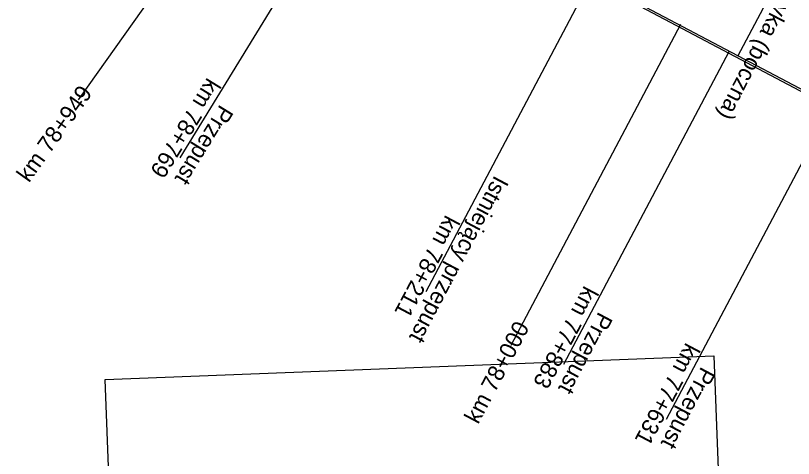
# Model space of a CAD drawing. Extents: x 6540402 to 6566579, y 5525343 to 5532423.
# Drawn here: x 6540402 to 6542041, y 5526352 to 5527285 of the extents above; entities that cross this region are included whole.
import ezdxf

# ---------------------------------------------------------------- set-up
doc = ezdxf.new("R2010")
doc.units = 0
for name, color, linetype in [('TOR_PS_OPIS_T-hektometry projektowane', 7, 'Continuous'), ('TOR_PS_OPIS_T-opisy dodatkowe', 7, 'Continuous'), ('TOR_PS_T-tory projektowane', 7, 'Continuous')]:
    doc.layers.add(name, color=color, linetype=linetype)

msp = doc.modelspace()

# ---------------------------------------------------------------- linework, layer by layer
at = {"layer": 'DEFPOINTS'}
msp.add_lwpolyline([(6541918.8, 5525392.9), (6540636.2, 5525343.2), (6540590.7, 5526518.4), (6541873.3, 5526568)], close=True, dxfattribs=at)
at = {"layer": 'TOR_PS_OPIS_T-hektometry projektowane'}
for points in [[(6540977.5, 5527731.7), (6540533.8, 5527107.2)], [(6541803.2, 5527266.3), (6541445.6, 5526590)]]:
    msp.add_lwpolyline(points, dxfattribs=at)
at = {"layer": 'TOR_PS_OPIS_T-opisy dodatkowe'}
for p, q in [((6542271.8, 5527857.1), (6541923.5, 5527198.5)), ((6541138.1, 5527620.4), (6540748.2, 5526985.5)), ((6541615, 5527361.7), (6541266.7, 5526703.1)), ((6541904.9, 5527208.4), (6541556.7, 5526549.8)), ((6542121.3, 5527092.8), (6541773, 5526434.2))]:
    msp.add_line(p, q, dxfattribs=at)
at = {"layer": 'TOR_PS_T-tory projektowane'}
for p, q in [((6542564.4, 5526861.3), (6541343.1, 5527507.1)), ((6542565.7, 5526856), (6541344.1, 5527502))]:
    msp.add_line(p, q, dxfattribs=at)

# ---------------------------------------------------------------- texts
at = {"layer": 'TOR_PS_OPIS_T-hektometry projektowane'}
for s, rotation, p in [('km 78+949', 54.6087, (6540430.4, 5526931.4)), ('km 78+000', 62.1299, (6541377, 5526422.7))]:
    msp.add_text(s, height=35, rotation=rotation, dxfattribs=at).set_placement(p)
at = {"layer": 'TOR_PS_OPIS_T-opisy dodatkowe'}
for s, rotation, p in [('Wiadukt kolejowy nad ul. Asnyka (boczna)', 242.8298, (6542280.9, 5527856)), ('km 78+769', 238.4471, (6540806.4, 5527155.8)), ('Przepust', 238.4471, (6540833.2, 5527099.2)), ('Istniejący przepust', 242.1299, (6541411.9, 5526950)), ('km 78+211', 242.1299, (6541308.5, 5526866.7)), ('km 77+883', 242.1299, (6541600.7, 5526717.7)), ('Przepust', 242.1299, (6541631.1, 5526662.8)), ('km 77+631', 242.1299, (6541814.8, 5526597.8)), ('Przepust', 242.1299, (6541847.4, 5526547.2))]:
    msp.add_text(s, height=35, rotation=rotation, dxfattribs=at).set_placement(p)

doc.saveas('drawing.dxf')
